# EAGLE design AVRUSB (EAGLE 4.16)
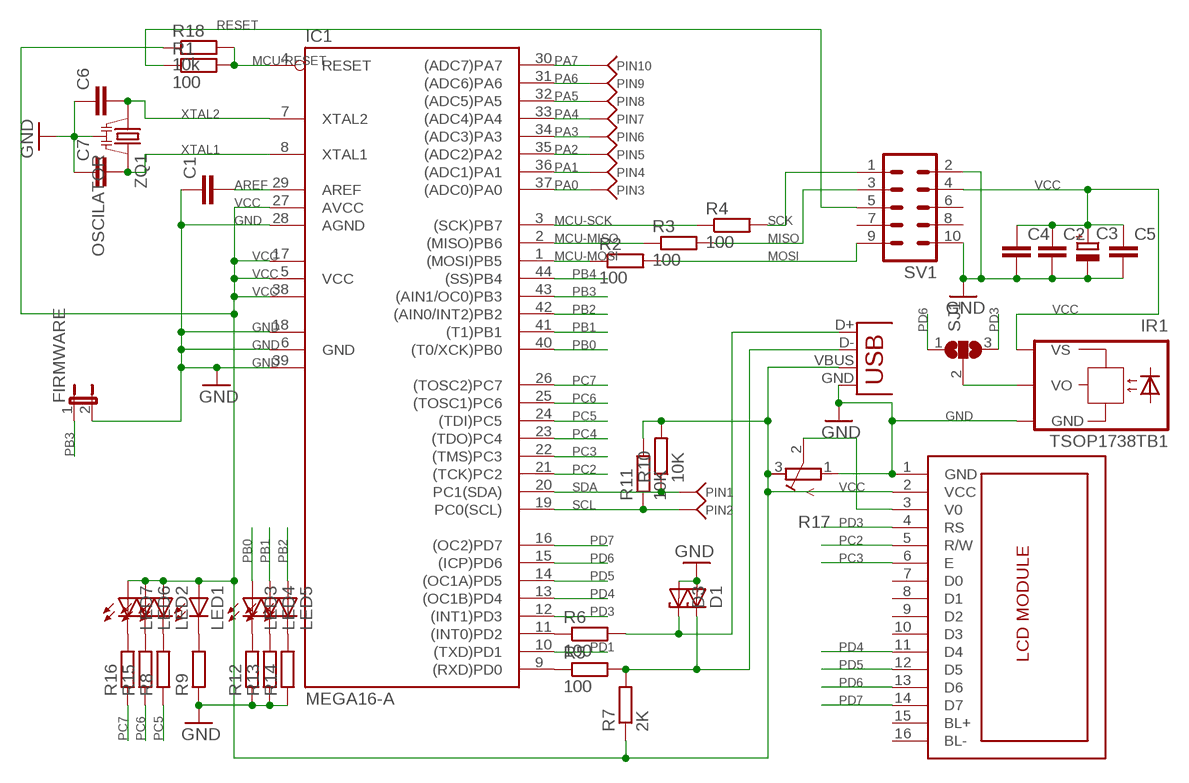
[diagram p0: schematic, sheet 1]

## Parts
C1  C-EUC1005  [C1005]
C2  C-EUC1210  [C1210]
C3  CPOL-EU140CLH-0810  [140CLH-0810]
C4  C-EUC1206  [C1206]
C5  C-EUC1206  [C1206]
C6  C-EUC1005  [C1005]
C7  C-EUC1005  [C1005]
D1  ZENER-DIODESOD80C  [SOD80C]
D3  ZENER-DIODESOD80C  [SOD80C]
FIRMWARE  JP1E  [JP1]
IC1  MEGA16-A  [TQFP44]
IR1  TSOP1738TB1  [TSOP17_TB1]
LCD1  LCD  [LCD1]
LED1  LEDCHIPLED_1206  [CHIPLED_1206]
LED2  LEDCHIPLED_1206  [CHIPLED_1206]
LED3  LEDCHIPLED_1206  [CHIPLED_1206]
LED4  LEDCHIPLED_1206  [CHIPLED_1206]
LED5  LEDCHIPLED_1206  [CHIPLED_1206]
LED6  LEDCHIPLED_1206  [CHIPLED_1206]
LED7  LEDCHIPLED_1206  [CHIPLED_1206]
PIN1  PINSMD2  [PIN-T2]
PIN2  PINSMD2  [PIN-T2]
PIN3  PINSMD2  [PIN-T2]
PIN4  PINSMD2  [PIN-T2]
PIN5  PINSMD2  [PIN-T2]
PIN6  PINSMD2  [PIN-T2]
PIN7  PINSMD2  [PIN-T2]
PIN8  PINSMD2  [PIN-T2]
PIN9  PINSMD2  [PIN-T2]
PIN10  PINSMD2  [PIN-T2]
R1  100  R-EU_M3216  [M3216]
R2  100  R-EU_M3216  [M3216]
R3  100  R-EU_M3216  [M3216]
R4  100  R-EU_M3216  [M3216]
R5  100  R-EU_M3216  [M3216]
R6  100  R-EU_M3216  [M3216]
R7  2K  R-EU_M3216  [M3216]
R8  R-EU_M3216  [M3216]
R9  R-EU_M3216  [M3216]
R10  10K  R-EU_M3216  [M3216]
R11  10K  R-EU_M3216  [M3216]
R12  R-EU_M3216  [M3216]
R13  R-EU_M3216  [M3216]
R14  R-EU_M3216  [M3216]
R15  R-EU_M3216  [M3216]
R16  R-EU_M3216  [M3216]
R17  R-TRIMM64Y  [RTRIM64Y]
R18  10k  R-EU_M3216  [M3216]
SJ1  SJ2WW  [SJ_2W]
SV1  ML10  [ML10]
X1  USB-B-H  [USB-B-H]
ZQ1  OSCILATOR  [OSCIL]

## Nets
AREF: C1.2 IC1.29(AREF)
D+: D3.C R6.2 X1.D+
D-: D1.C R5.2 R7.2 X1.D-
GND: C1.1 C2.2 C3.- C4.2 C5.2 C6.1 C7.1 D1.A D3.A FIRMWARE.2 IC1.6(GND) IC1.18(GND1) IC1.28(AGND) IC1.39(GND2) IR1.GND LCD1.1(GND) R9.1 R12.1 R13.1 R14.1 R17.1(E) SV1.2 SV1.10 X1.GND ZQ1.P$2
IRDATA: IR1.VO SJ1.2
MCU-MISO: IC1.2((MISO)PB6) R3.1
MCU-MOSI: IC1.1((MOSI)PB5) R2.1
MCU-RESET: IC1.4(RESET) R1.2 R18.2
MCU-SCK: IC1.3((SCK)PB7) R4.1
MISO: R3.2 SV1.3
MOSI: R2.2 SV1.9
N$1: LED3.C R12.2
N$2: LED4.C R13.2
N$3: LED5.C R14.2
N$4: LCD1.3(V0) R17.2(S)
N$5: LED6.C R15.2
N$6: LED7.C R16.2
N$10: IC1.9((RXD)PD0) R5.1
N$11: IC1.11((INT0)PD2) R6.1
N$25: LED2.C R8.2
N$31: LED1.C R9.2
PA0: IC1.37((ADC0)PA0) PIN3.P$1(P)
PA1: IC1.36((ADC1)PA1) PIN4.P$1(P)
PA2: IC1.35((ADC2)PA2) PIN5.P$1(P)
PA3: IC1.34((ADC3)PA3) PIN6.P$1(P)
PA4: IC1.33((ADC4)PA4) PIN7.P$1(P)
PA5: IC1.32((ADC5)PA5) PIN8.P$1(P)
PA6: IC1.31((ADC6)PA6) PIN9.P$1(P)
PA7: IC1.30((ADC7)PA7) PIN10.P$1(P)
PB0: IC1.40((T0/XCK)PB0) LED3.A
PB1: IC1.41((T1)PB1) LED4.A
PB2: IC1.42((AIN0/INT2)PB2) LED5.A
PB3: FIRMWARE.1 IC1.43((AIN1/OC0)PB3)
PB4: IC1.44((SS)PB4)
PC2: IC1.21((TCK)PC2) LCD1.5(R/W)
PC3: IC1.22((TMS)PC3) LCD1.6(E)
PC4: IC1.23((TDO)PC4)
PC5: IC1.24((TDI)PC5) R8.1
PC6: IC1.25((TOSC1)PC6) R15.1
PC7: IC1.26((TOSC2)PC7) R16.1
PD1: IC1.10((TXD)PD1)
PD3: IC1.12((INT1)PD3) LCD1.4(RS) SJ1.3
PD4: IC1.13((OC1B)PD4) LCD1.11(D4)
PD5: IC1.14((OC1A)PD5) LCD1.12(D5)
PD6: IC1.15((ICP)PD6) LCD1.13(D6) SJ1.1
PD7: IC1.16((OC2)PD7) LCD1.14(D7)
RESET: R1.1 SV1.5
SCK: R4.2 SV1.1
SCL: IC1.19(PC0(SCL)) PIN2.P$1(P) R11.1
SDA: IC1.20(PC1(SDA)) PIN1.P$1(P) R10.1
VCC: C2.1 C3.+ C4.1 C5.1 IC1.5(VCC) IC1.17(VCC1) IC1.27(AVCC) IC1.38(VCC2) IR1.VS LCD1.2(VCC) LED1.A LED2.A LED6.A LED7.A R7.1 R10.2 R11.2 R17.3(A) R18.1 SV1.4 X1.VBUS
XTAL1: C7.2 IC1.8(XTAL1) ZQ1.P$3
XTAL2: C6.2 IC1.7(XTAL2) ZQ1.P$1
Unconnected: LCD1.7(D0) LCD1.8(D1) LCD1.9(D2) LCD1.10(D3) SV1.6 SV1.7 SV1.8

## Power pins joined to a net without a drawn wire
BL+: LCD1.15(BL+)
BL-: LCD1.16(BL-)

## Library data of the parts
C1 C2 C4-C7 = rcl:C-EU: CAPACITOR, European symbol
C3 = rcl:CPOL-EU: POLARIZED CAPACITOR, European symbol
D1 D3 = diode:ZENER-DIODE: Z-Diode
FIRMWARE = jumper:JP1E: JUMPER
IC1 = atmel:MEGA16: MICROCONTROLLER 16 Kbytes FLASH 1 kbytes SRAM 512 bytes EEPROM USART 8-channel 10 bit ADC Source: avr.lbr
IR1 = telefunken:TSOP17*TB1: TSOP17..TB1 IR Receiver Modules for Remote Control Systems Source: http://www.vishay.com/docs/82042/82042.pdf
LCD1 = LevoROMS:LCD: Standartinis LCD modulis
LED1-LED7 = led:LED: LED
PIN1-PIN10 = LevoROMS:PIN*: PIN
R1-R16 R18 = rcl:R-EU_: RESISTOR, European symbol
R17 = rcl:R-TRIMM: Trimm resistor
SJ1 = jumper:SJ2W: SMD solder JUMPER
SV1 = con-ml:ML10: HARTING
X1 = con-usb:USB: USB Connectors
ZQ1 = LevoROMS:OSCILATOR: Keraminis rezonatorius su kondikais

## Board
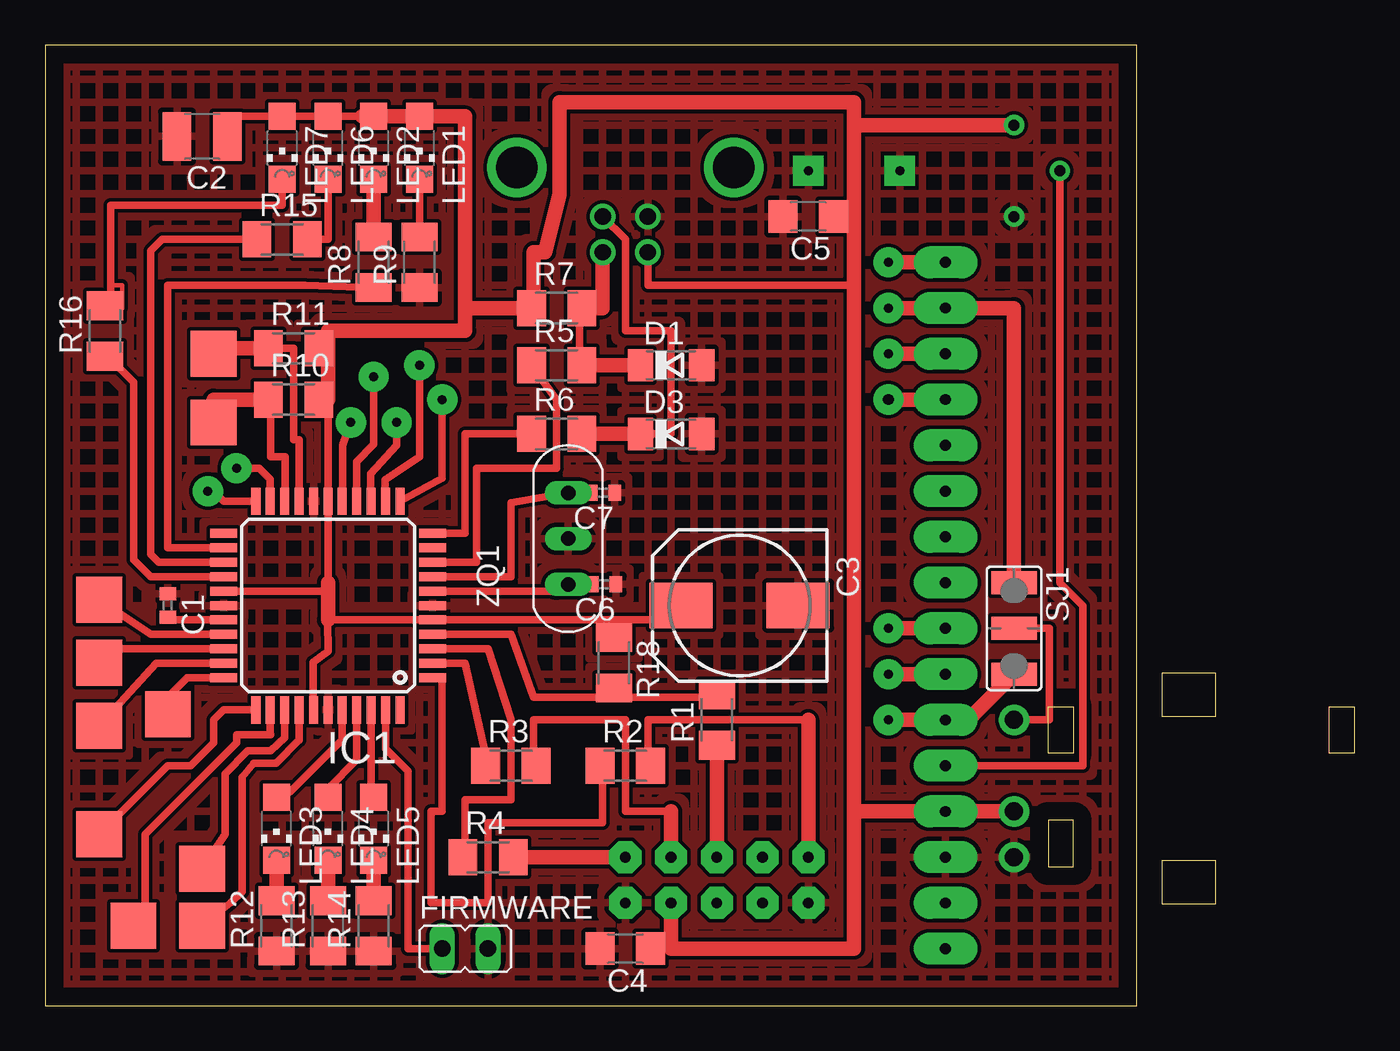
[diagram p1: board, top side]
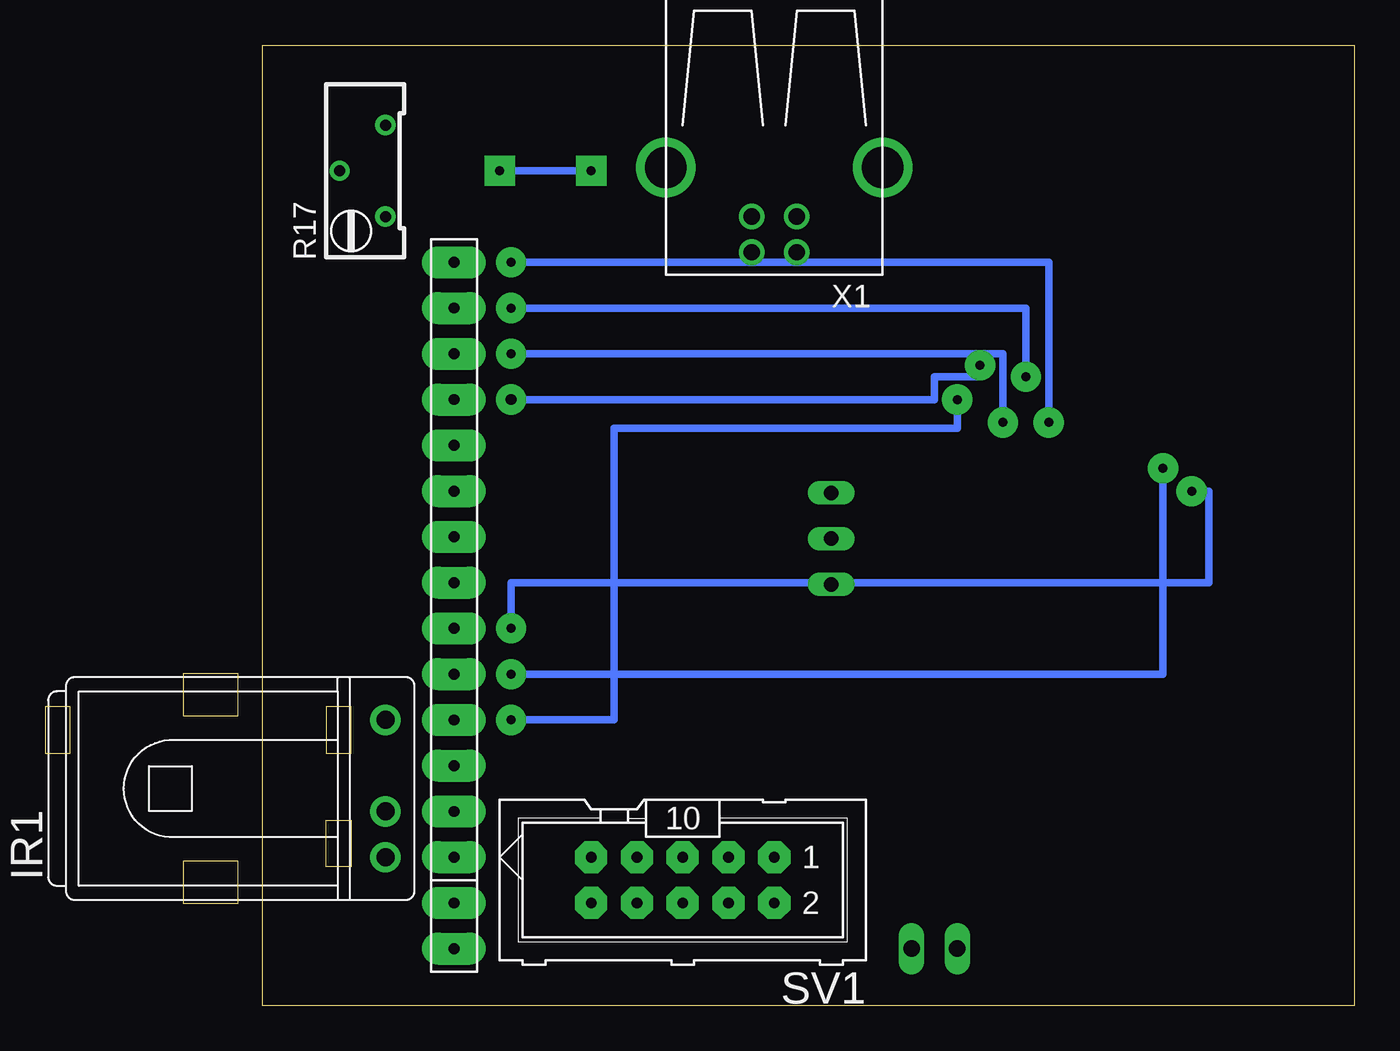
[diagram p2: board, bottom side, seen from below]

Size 72.71 x 53.33 mm. Coordinates in mm from the lower left corner, seen from the top.
Outline: 0,0 60.63,0 60.63,53.33 0,53.33 0,0
Copper layers (1*16): Top 0.035mm / dielectric 1.5mm / Bottom 0.035mm
Design rules "default": minimum track width 10mil, minimum drill 24mil, track to track 8mil, track to pad 8mil, pad to pad 8mil, via to via 8mil, smd to smd 8mil, copper to edge 40mil, drill to drill 8mil, minimum pad ring 10mil, minimum via ring 8mil, stop-mask expansion 4mil, vias tented up to drill 0mil, thermal gap 10mil

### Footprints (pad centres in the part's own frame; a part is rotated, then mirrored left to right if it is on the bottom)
C1005 = smd 0.7 x 0.9: 1 -0.65,0; 2 0.65,0
C1210 = smd 1.6 x 2.7: 1 -1.4,0; 2 1.4,0
140CLH-0810 = smd 3.5 x 2.5: + 3.25,0; - -3.25,0
C1206 = smd 1.6 x 1.8: 1 -1.4,0; 2 1.4,0
SOD80C = smd 1.4 x 1.8: A 1.7,0; C -1.7,0
JP1 = drill 0.914 long: 1 0,-1.27; 2 0,1.27
TQFP44 = smd 1.5 x 0.5: 1 -5.8,4; 2 -5.8,3.2; 3 -5.8,2.4; 4 -5.8,1.6; 5 -5.8,0.8; 6 -5.8,0; 7 -5.8,-0.8; 8 -5.8,-1.6; 9 -5.8,-2.4; 10 -5.8,-3.2; 11 -5.8,-4; 23 5.8,-4; 24 5.8,-3.2; 25 5.8,-2.4; 26 5.8,-1.6; 27 5.8,-0.8; 28 5.8,0; 29 5.8,0.8; 30 5.8,1.6; 31 5.8,2.4; 32 5.8,3.2; 33 5.8,4 | smd 0.5 x 1.5: 12 -4,-5.8; 13 -3.2,-5.8; 14 -2.4,-5.8; 15 -1.6,-5.8; 16 -0.8,-5.8; 17 0,-5.8; 18 0.8,-5.8; 19 1.6,-5.8; 20 2.4,-5.8; 21 3.2,-5.8; 22 4,-5.8; 34 4,5.8; 35 3.2,5.8; 36 2.4,5.8; 37 1.6,5.8; 38 0.8,5.8; 39 0,5.8; 40 -0.8,5.8; 41 -1.6,5.8; 42 -2.4,5.8; 43 -3.2,5.8; 44 -4,5.8
TSOP17_TB1 = drill 1 pad 1.676 round: GND 0,-3.81; VO 0,3.81; VS 0,-1.27
LCD1 = drill 0.6 pad 1.778 long: 1 12.7,-1.27; 2 10.16,-1.27; 3 7.62,-1.27; 4 5.08,-1.27; 5 2.54,-1.27; 6 0,-1.27; 7 -2.54,-1.27; 8 -5.08,-1.27; 9 -7.62,-1.27; 10 -10.16,-1.27; 11 -12.7,-1.27; 12 -15.24,-1.27; 13 -17.78,-1.27; 14 -20.32,-1.27; 15 17.78,-1.27; 16 15.24,-1.27
CHIPLED_1206 = smd 1.5 x 1.5: A 0,-1.75; C 0,1.75
PIN-T2 = smd 2.54 x 2.54: P$1 0,0
M3216 = smd 1.6 x 2: 1 -1.4,0; 2 1.4,0
RTRIM64Y = drill 0.61 round: 1 0,-2.54; 2 -2.54,0; 3 0,2.54
SJ_2W = smd 1.27 x 2.54: 1 -2.54,0; 2 0,0; 3 2.54,0
ML10 = drill 0.6 pad 1.778 octagon: 1 -5.08,-1.27; 2 -5.08,1.27; 3 -2.54,-1.27; 4 -2.54,1.27; 5 0,-1.27; 6 0,1.27; 7 2.54,-1.27; 8 2.54,1.27; 9 5.08,-1.27; 10 5.08,1.27
USB-B-H = drill 0.914 round: D+ 0,1.25; D- 1.981,1.25; GND 0,-1.25; VBUS 1.981,-1.25 | drill 2.286 round: P$1 -2.718,-6.02; P$2 -2.718,6.02
OSCIL = drill 0.8 long: P$1 -2.54,0; P$2 0,0; P$3 2.54,0

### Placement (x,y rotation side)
C1  6.82,22.22 270 top
C2  8.73,48.25 180 top
C3  38.57,22.22 180 top
C4  32.22,3.17 180 top
C5  42.38,43.81 180 top
C6  31.05,23.39 180 top
C7  30.98,28.47 180 top
D1  34.76,35.55 0 top
D3  34.76,31.74 0 top
FIRMWARE  23.33,3.17 270 top
IC1  15.71,22.22 180 top
IR1  53.81,12.06 0 bottom
LCD1  48.73,20.95 270 bottom
LED1  20.79,47.62 180 top
LED2  18.25,47.62 180 top
LED3  12.85,9.84 180 top
LED4  15.71,9.84 180 top
LED5  18.25,9.84 180 top
LED6  15.71,47.62 180 top
LED7  13.17,47.62 180 top
PIN1  9.36,32.38 0 top
PIN2  9.36,36.19 0 top
PIN3  8.73,4.44 0 top
PIN4  8.73,7.61 0 top
PIN5  4.91,4.44 0 top
PIN6  3.01,9.52 0 top
PIN7  6.82,16.19 0 top
PIN8  3.01,15.55 0 top
PIN9  3.01,19.05 0 top
PIN10  3.01,22.54 0 top
R1  37.3,15.87 90 top
R2  32.22,13.33 0 top
R3  25.87,13.33 0 top
R4  24.6,8.25 0 top
R5  28.41,35.55 0 top
R6  28.41,31.74 0 top
R7  28.41,38.73 0 top
R8  18.25,41.27 90 top
R9  20.79,41.27 90 top
R10  13.8,33.65 0 top
R11  13.8,36.51 0 top
R12  12.85,4.44 90 top
R13  15.71,4.44 90 top
R14  18.25,4.44 90 top
R15  13.17,42.54 0 top
R16  3.33,37.46 90 top
R17  53.81,46.35 0 bottom
R18  31.59,19.05 270 top
SJ1  53.81,20.95 270 top
SV1  37.3,6.98 180 bottom
X1  32.22,43.81 270 bottom
ZQ1  29.05,25.93 90 top

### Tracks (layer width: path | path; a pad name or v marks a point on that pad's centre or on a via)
AREF
  Top 0.406: 6.82,21.59 C1.2 6.82,21.42 IC1.29
D+
  Top 0.406: D3.C 33.49,31.74 34.76,31.74 34.76,37.46 32.22,37.46 32.22,42.54 30.97,43.79 X1.D+
  Top 0.813: R6.2 33.49,31.74 | X1.D+ 30.95,43.81
D-
  Top 0.406: R5.2 29.68,36.19 29.68,38.73
  Top 0.813: R5.2 D1.C | X1.D- 30.97,38.75 30.95,38.73 29.68,38.73 R7.2
GND  (via drill 0.5 pad 1.68)
  Bottom 0.406: v42.38,46.35 v47.46,46.35
  pour Top (hatched): -24.93,60.32 -23.66,60.32 -23.66,-17.15 74.13,-17.15 74.13,60.32
IRDATA
  Top 0.406: IR1.VO 55.78,15.87 55.78,20.95 SJ1.2
MCU-MISO
  Top 0.406: R3.1 24.6,13.33 23.33,19.02 IC1.2
MCU-MOSI
  Top 0.406: IC1.1 22.06,18.22 22.06,10.79 21.42,10.79 21.42,5.71 24.6,5.71 24.6,10.15 30.95,10.15 30.95,13.33 R2.1
MCU-RESET
  Top 0.406: IC1.4 25.87,20.62 27.14,17.14 31.59,17.14 | R1.2 37.3,17.14 31.59,17.14 | 31.59,17.14 R18.2
MCU-SCK
  Top 0.406: IC1.3 24.6,19.82 25.87,15.87 25.87,11.42 23.33,11.42 23.33,8.25 R4.1
MISO
  Top 0.406: R3.2 27.14,13.33 27.14,15.87 32.22,15.87 32.22,10.79 34.76,10.79
  Top 0.813: 34.76,10.79 SV1.3
MOSI
  Top 0.406: R2.2 33.49,13.33 33.49,15.87 42.38,15.87
  Top 0.813: 42.38,15.87 SV1.9
N$1
  Top 0.813: R12.2 LED3.C
N$2
  Top 0.406: R13.2 15.71,5.71
  Top 0.813: R13.2 LED4.C
N$3
  Top 0.406: R14.2 18.25,5.71
  Top 0.813: R14.2 LED5.C
N$4
  Top 0.406: R17.2 56.35,23.49 57.62,22.22 57.62,13.33 LCD1.3
N$5
  Top 0.406: R15.2 15.71,42.54 LED6.C
N$6
  Top 0.254: R16.2 4.28,38.73 4.28,40 3.64,40
  Top 0.406: LED7.C 13.17,44.45 3.64,44.45 3.64,40 3.64,39.36
N$10
  Top 0.406: IC1.9 23.97,24.62 23.97,29.84 28.41,29.84 28.41,33.65 R5.1
N$11
  Top 0.406: IC1.11 23.33,26.22 23.33,31.74 R6.1 27.14,31.11
N$25
  Top 0.813: R8.2 LED2.C
N$31
  Top 0.406: 20.79,46.35 LED1.C R9.2 20.79,42.54
PA0
  Top 0.406: IC1.37 14.11,14.93 14.12,14.73 14.12,14.76 12.82,13.46 11.58,13.46 10.95,12.69 10.95,6.34 10.31,5.71 PIN3.P$1
PA1
  Top 0.406: IC1.36 13.31,14.87 12.54,14.16 11.27,14.16 9.99,12.88 9.99,9.52 PIN4.P$1
PA2
  Top 0.406: PIN5.P$1 5.55,5.71 5.55,9.52 10.63,14.6 10.63,15.05 12.54,15.05 12.51,15.16 IC1.35
PA3
  Top 0.406: IC1.34 9.91,16.42 9.36,15.87 9.36,14.6 8.09,13.33 6.82,13.33 PIN6.P$1
PA4
  Top 0.406: IC1.33 7.9,18.22 6.82,17.14 PIN7.P$1
PA5
  Top 0.406: IC1.32 6.16,19.02 PIN8.P$1
PA6
  Top 0.406: IC1.31 3.15,19.82 PIN9.P$1
PA7
  Top 0.406: IC1.30 5.88,20.62 PIN10.P$1
PB0
  Top 0.406: IC1.40 16.51,14.77 13.61,11.87 12.85,11.74 LED3.A
PB1
  Top 0.406: LED4.A 15.71,12.06 17.31,13.66 IC1.41
PB2
  Top 0.406: LED5.A 18.25,11.74 18.11,11.88 IC1.42
PB3
  Top 0.406: IC1.43 18.91,14.26 20.16,13.01 20.16,3.17 FIRMWARE.1
PC2  (via drill 0.5 pad 1.68)
  Top 0.406: IC1.21 12.51,29.23 11.9,29.84 v10.63,29.84
  Top 0.813: v46.82,18.41 LCD1.5
  Bottom 0.406: v10.63,29.84 10.63,18.41 v46.82,18.41
PC3  (via drill 0.5 pad 1.68)
  Top 0.406: v9.04,28.57 9.36,28.57 9.91,28.02 IC1.22
  Top 0.813: v46.82,20.95 LCD1.6
  Bottom 0.406: 9.36,28.57 v9.04,28.57 8.09,28.57 8.09,23.49 46.82,23.49 v46.82,20.95
PC5
  Top 0.406: IC1.24 6.82,25.42 6.82,40 14.44,40 R8.1
PC6
  Top 0.406: IC1.25 6.32,24.62 5.87,25.08 5.87,41.91 6.5,42.54 R15.1
PC7
  Top 0.406: IC1.26 5.86,23.82 4.91,24.76 4.91,34.6 3.46,36.06 R16.1
PD3  (via drill 0.5 pad 1.68)
  Top 0.406: IC1.12 22.06,29.29 v22.06,33.65
  Top 0.813: v46.82,15.87 LCD1.4 51.27,15.87 SJ1.3
  Bottom 0.406: v46.82,15.87 41.11,15.87 41.11,32.06 22.06,32.06 v22.06,33.65
PD4  (via drill 0.5 pad 1.68, 0.6 pad 1.68)
  Top 0.406: IC1.13 18.88,28.02 18.88,29.2 20.79,30.48 v20.79,35.55
  Top 0.813: v46.82,33.65 LCD1.11
  Bottom 0.406: v46.82,33.65 23.33,33.65 23.33,34.92 20.79,34.92 v20.79,35.55
PD5  (via drill 0.5 pad 1.68)
  Top 0.406: IC1.14 18.09,28.02 18.09,29.52 19.52,31.11 v19.52,32.38
  Top 0.813: v46.82,36.19 LCD1.12
  Bottom 0.406: v46.82,36.19 19.52,36.19 v19.52,32.38
PD6  (via drill 0.5 pad 1.68)
  Top 0.406: IC1.15 17.3,28.02 17.3,30.19 18.25,31.17 v18.25,34.92
  Top 0.813: v46.82,38.73 LCD1.13 53.81,38.73 SJ1.1
  Bottom 0.406: v46.82,38.73 18.25,38.73 v18.25,34.92
PD7  (via drill 0.5 pad 1.68)
  Top 0.406: IC1.16 16.54,28.02 16.54,31.11 v16.98,32.38
  Top 0.813: v46.82,41.27 LCD1.14
  Bottom 0.406: v46.82,41.27 16.98,41.27 v16.98,32.38
RESET
  Top 0.813: SV1.5 R1.1
SCK
  Top 0.813: R4.2 SV1.1
SCL
  Top 0.406: 9.36,36.51 PIN2.P$1 | IC1.19 14.12,28.02 14.12,31.43 13.8,31.43 13.8,36.51 R11.1
  Top 0.813: R11.1 9.36,36.51
SDA
  Top 0.406: PIN1.P$1 9.36,33.65 | IC1.20 13.33,28.02 13.33,30.48 12.54,30.48 12.54,33.65 R10.1
  Top 0.813: 9.36,33.65 R10.1
VCC
  Top 0.406: 15.68,23.02 IC1.27 | 15.68,23.02 15.71,23.02 15.71,23.49 15.71,27.93 | IC1.38 14.88,16.45 14.88,19.08 15.71,19.68 15.68,23.02 | 15.71,21.42 IC1.5 31.59,21.42 | 15.71,28.57 IC1.17 15.71,27.93 | 15.71,28.57 15.71,33.65 R10.2 | R7.1 27.14,38.73 | LED2.A 18.25,48.89 | 15.71,27.93 15.71,28.57 | 35.4,22.22 C3.+ | 31.59,21.42 35.4,21.42 | 15.71,36.51 R11.2 | 34.76,3.17 C4.1 | 44.92,43.81 C5.1 | X1.VBUS 33.47,40.02 33.49,40 44.92,40 | 17.62,49.37 LED6.A | LED6.A 15.71,48.89 | LED6.A LED7.A | LED7.A 13.17,48.89 | C2.1 9.99,48.25 9.99,49.37 LED7.A | 31.59,21.42 R18.1
  Top 0.813: 15.71,23.49 15.71,21.42 | 27.14,38.73 27.14,41.83 27.77,41.83 28.57,45.05 28.57,50.16 44.92,50.16 44.92,48.89 | 23.33,38.73 23.33,37.46 15.71,37.46 15.71,36.19 | 23.33,38.73 R7.1 | 15.71,33.65 15.71,36.19 | 17.62,49.37 LED2.A LED1.A 23.33,49.37 23.33,38.73 | SV1.4 34.76,3.17 44.92,3.17 44.92,10.79 | 44.92,48.89 44.92,43.81 44.92,40 44.92,10.79 | 35.4,21.42 35.4,22.22 | 44.92,10.79 LCD1.2 IR1.VS | 15.71,36.19 15.71,36.51 | 44.92,48.89 R17.3
XTAL1
  Top 0.406: IC1.8 25.87,23.82 25.87,27.93 ZQ1.P$3 C7.2
XTAL2
  Top 0.406: IC1.7 29.05,23.02 ZQ1.P$1 C6.2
